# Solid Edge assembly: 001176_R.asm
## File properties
Last saved by: morva
Revision: 33
Application: Solid Edge
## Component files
001176-7_R.par
001176-10_R.par
001176-3_R.par
001176-13_R.par
001176-9_R.par
001176-5_R.par
001176-4_R.par
001176-2_R.par
001176-1_R.par
001176-12_R.par
001176-11_R.par
001176-6_R.par
001176-8_R.par
